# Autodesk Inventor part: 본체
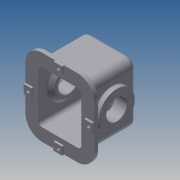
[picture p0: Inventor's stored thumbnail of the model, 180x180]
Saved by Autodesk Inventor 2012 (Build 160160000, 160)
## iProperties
Created: 2014-11
Part Number: 본체
Material: 알루미늄-6061
Document SubType Name: Modeling
Designer: Owner
Density: 2.71 g/cm^3
Mass: 2881.87 g
Surface Area: 2079.03 cm^2
Volume: 1063.42 cm^3
Author: Owner
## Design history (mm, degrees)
sketch "스케치1"
  geometry: L1 (-87, 0)-(87, 0); L2 (-87, 10)-(87, 10); L3 (-87, 0)-(-87, 10); L4 (87, 0)-(87, 10); L5 (-65, 10)-(-65, 128); L6 (-65, 128)-(65, 128); L7 (65, 128)-(65, 10); 1 further point
  constraints: 14 end point, 3 parallel, 3 perpendicular, 2 point on line, 1 horizontal
  dimensions: "d0" = 87 distance of L1.start point (0, 0); "d1" = 174 distance of L1.start L1.end; "d2" = 10 distance of L1.end L2.end; "d3" = 118 distance of L6.end L7.end; "d4" = 65 distance from line of L5 point (0, 0); "d5" = 65 distance from line of point (0, 0) L7
extrude "돌출1" new body sketch "스케치1" stored distance "d6" = 196; taper "d7" = 0 deg
extrude "돌출2" join sketch "스케치1" stored distance "d8" = 152; taper "d9" = 0 deg
fillet "모깎기1" dims "d10" = 20
fillet "모깎기2" dims "d11" = 10
fillet "모깎기3" dims "d12" = 42
sketch "스케치2"
  geometry: L1 (118, -76)-(10, -76) reference; L2 (10, -76)-(10, -98) reference; L3 (10, -98)-(0, -98) reference; L4 (0, -98)-(0, 98) reference; L5 (0, 98)-(10, 98) reference; L6 (10, 98)-(10, 76) reference; L7 (10, 76)-(118, 76) reference; L8 (128, 66)-(128, -66) reference; L9 (0, 0)-(68, 0); L10 (68, 0)-(152.121, -17.88); L11 (68, 0)-(68, -119.554); A1 r 10 centre (118, -66) between (118, -76) and (128, -66) reference; A2 r 10 centre (118, 66) between (128, 66) and (118, 76) reference
  constraints: 6 end point, 2 perpendicular
  dimensions: "d13" = 68 distance from line of L9.end L4; "d14" = 78 deg angle of L10 L11; "d15" = 86 distance of L9.end L10.end
  node "절단 모서리 투영1"
node "작업 평면1"
sketch "스케치3"
  geometry: C1 r 31 at (0, 0); 2 further points
  constraints: 1 centre point, 1 coincident
  dimensions: "d16" = 62 diameter of C1
extrude "돌출3" join sketch "스케치3" distance "d17" = 100; taper "d18" = 0 deg
feature "쉘1" dims "d19" = 10
sketch "스케치4"
  geometry: C1 r 21 at (0, 0) reference; 1 further point
extrude "돌출4" join sketch "스케치4" stored distance "d20" = 100; taper "d21" = 0 deg
fillet "모깎기4" dims "d22" = 3
sketch "스케치5"
  geometry: C1 r 31 at (0, 0) reference; C2 r 21 at (0, 0); 1 further point
  constraints: 1 centre point, 1 coincident
  dimensions: "d23" = 42 diameter of C2
extrude "돌출5" cut sketch "스케치5" distance "d24" = 25; taper "d25" = 0 deg
sketch "스케치6"
  geometry: C1 r 21 at (0, 0) reference; C2 r 15 at (0, 0); 1 further point
  constraints: 1 centre point, 1 coincident
  dimensions: "d26" = 30 diameter of C2
extrude "돌출6" cut sketch "스케치6" distance "d27" = 50; taper "d28" = 0 deg
fillet "모깎기5" dims "d29" = 0.3
fillet "모깎기6" dims "d30" = 3
sketch "스케치7"
  geometry: L1 (-87, 10)-(-65, 10) reference; L2 (-65, 10)-(-65, 118) reference; L3 (-55, 128)-(-31.376, 128) reference; L4 (-25.037, 155.921)-(-10.337, 155.921) reference; L5 (-16.136, 130.363)-(-7.542, 130.363) reference; L6 (-10.814, 118)-(-52, 118) reference; L7 (-55, 115)-(-55, 0) reference; L8 (-55, 0)-(-87, 0) reference; L9 (-87, 0)-(-87, 10) reference; L10 (65, 10)-(87, 10) reference; L11 (87, 10)-(87, 0) reference; L12 (87, 0)-(55, 0) reference; L13 (55, 0)-(55, 115) reference; L14 (52, 118)-(10.814, 118) reference; L15 (7.542, 130.363)-(16.136, 130.363) reference; L16 (10.337, 155.921)-(25.037, 155.921) reference; L17 (31.376, 128)-(55, 128) reference; L18 (65, 118)-(65, 10) reference; L19 (65, 68)-(45, 68); L20 (45, 68)-(45, 103.5); L21 (55, 68)-(55, 113.5); L22 (99.459, 113.5)-(14.158, 113.5); L23 (55, 113.5)-(45, 103.5); A1 r 10 centre (-55, 118) between (-55, 128) and (-65, 118) reference; A2 r 3 centre (-52, 115) between (-52, 118) and (-55, 115) reference; A3 r 3 centre (52, 115) between (55, 115) and (52, 118) reference; A4 r 10 centre (55, 118) between (65, 118) and (55, 128) reference; 11 further points; 6 other entities
  constraints: 10 end point, 3 perpendicular, 2 point on line, 1 midpoint, 10 other
  dimensions: "d31" = 68 distance between parallel lines of L8 L19; "d32" = 10 distance between parallel lines of L21 L20; "d33" = 91 diameter of L22 L19; "d34" = 71 diameter of L20.end L19
revolve "회전1" sketch "스케치7" stored, may be unused: angle "d35" = 90 deg
sketch "스케치8"
  geometry: C1 r 35.5 at (0, 0) reference; C2 r 26 at (0, 0); 1 further point
  constraints: 1 centre point, 1 coincident
  dimensions: "d36" = 52 diameter of C2
extrude "돌출7" cut sketch "스케치8" distance "d37" = 50; taper "d38" = 0 deg
sketch "스케치9"
  geometry: C1 r 26 at (56, 58) reference; C2 r 45.5 at (56, 58); 1 further point
  constraints: 1 centre point, 1 coincident
  dimensions: "d39" = 91 diameter of C2
extrude "돌출8" join sketch "스케치9" distance "d40" = 12; taper "d41" = 0 deg
sketch "스케치10" dims "d42" = 70
  geometry: C1 r 45.5 at (0, 0) reference; 3 further points
  constraints: 1 coincident, 1 vertical alignment, 2 other
hole "구멍1" sketch "스케치10" at (0, 35) diameter "d43" = 3.242; stored, may be unused: countersink angle "d47" = 90 deg, drill point angle "d49" = 118 deg; dims "d44" = 13, "d45" = 4, "d46" = 2, "d48" = 16
fillet "모깎기7" dims "d53" = 3
fillet "모깎기8" dims "d54" = 3
chamfer "모따기1" distance "d55" = 1; stored, may be unused: second distance "d56" = 2, angle "d57" = 45 deg
chamfer "모따기2" distance "d58" = 1; stored, may be unused: second distance "d59" = 2, angle "d60" = 45 deg
sketch "스케치11"
  geometry: L1 (-42, -42)-(-42, -154) reference; L2 (-42, -109)-(-22, -109); L3 (-22, -109)-(-22, -87); L4 (-22, -87)-(-42, -87); L5 (-42, -87)-(-42, -109); 1 further point
  constraints: 8 end point, 2 parallel, 1 horizontal, 1 perpendicular, 1 point on line
  dimensions: "d61" = 11 distance from line of L2 point (45, -98); "d62" = 11 distance from line of L4 point (45, -98); "d63" = 20 distance between parallel lines of L1 L3
extrude "돌출9" join sketch "스케치11" distance "d64" = 5; taper "d65" = 0 deg
sketch "스케치12"
  geometry: L1 (0, -196)-(90, -196) reference; L2 (34, -196)-(56, -196); L3 (56, -196)-(56, -176); L4 (56, -176)-(34, -176); L5 (34, -176)-(34, -196); 1 further point
  constraints: 8 end point, 2 parallel, 1 horizontal, 1 perpendicular, 1 point on line
  dimensions: "d66" = 11 distance from line of point (45, -98) L3; "d67" = 11 distance from line of point (45, -98) L5; "d68" = 20 distance of L2.end L3.end
extrude "돌출10" join sketch "스케치12" distance "d69" = 5; taper "d70" = 0 deg
sketch "스케치13"
  geometry: L1 (132, -42)-(132, -154) reference; 2 further points
  dimensions: "d71" = 10 distance from line of point (122, -98) L1
hole "구멍2" sketch "스케치13" at (122, -98) diameter "d72" = 9; stored, may be unused: countersink angle "d76" = 90 deg, drill point angle "d78" = 118 deg; dims "d73" = 9, "d74" = 14, "d75" = 8.6, "d77" = 16
sketch "스케치14"
  geometry: L1 (90, 0)-(0, 0) reference; 2 further points
  dimensions: "d79" = 10 distance from line of point (45, -10) L1
hole "구멍3" sketch "스케치14" at (45, -10) diameter "d80" = 9; stored, may be unused: countersink angle "d84" = 90 deg, drill point angle "d86" = 118 deg; dims "d81" = 9, "d82" = 14, "d83" = 8.6, "d85" = 16
fillet "모깎기9" dims "d91" = 3
sketch "스케치17"
  geometry: L1 (45, 0)-(11, 0) reference; 2 further points
  constraints: 1 other
  dimensions: "d96" = 92 distance from line of L1 point (0, 92); "d97" = 0 horizontal distance of point (0, 92) point (0, 0)
feature "엠보싱3" sketch "스케치17" dims "d98" = 1, "d99" = 0
node "솔리드1"
pattern_circular "원형 패턴1" dims angle "d51" = 360 deg
mirror "대칭1"
mirror "대칭2"
mirror "대칭3"
mirror "대칭4"
mirror "대칭5"
mirror "대칭6"
mirror "대칭7"
node "절단 모서리 투영2"
